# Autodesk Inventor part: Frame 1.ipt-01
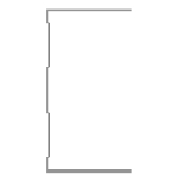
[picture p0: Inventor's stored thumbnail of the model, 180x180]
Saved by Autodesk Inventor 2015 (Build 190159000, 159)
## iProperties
Created: 2015-04
Part Number: Frame 1.ipt-01
Material: Aluminum 6061
Description: Kévin Novo
Document SubType Name: Modeling
Standard: Kevin
Designer: suporte
Standards Organization: Kevin
Language: en-US
Size Designation: (Unnamed 1)
Categories: <MemberInstance><Categories><Category DisplayName="Structural Shapes" InternalName="089c4875-fa83-4c05-b084-43b9cc11f5ed" Mnemonic="GRDR"><CategoryParameter Dis
Density: 2.7 g/cm^3
Appearance: Aluminum - Flat
IsCustomPart: 1
G_L: 1150,000 mm
G_W: 50,000 mm
G_H: 75,000 mm
+3D70875A-E5A9-4FDA-85E3-2CF6FFD64956+CUTDETAIL1: Cut
+E4C8F863-C9A0-4110-9EB7-EA6FC54E2E86+CUTDETAIL2: Cut
_CCFamilyMember: 1
_CCFamilyDisplayName: Kévin - Kévin Novo
_FrameMemberDoc: Frame Member File
_Version: 15.0.0
_GetPNFromCC: 1
Author: suporte
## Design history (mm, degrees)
node "Start Plane"
node "End Plane"
sketch "Sketch"
  geometry: L1 (24.7, 37.5)-(24.7, 36.9); L2 (24.7, 36.9)-(-24.7, 36.9); L3 (-24.7, -36.9)-(24.7, -36.9); L4 (24.7, -36.9)-(24.7, -37.5); L5 (24.7, -37.5)-(-25.3, -37.5); L6 (-25.3, 37.5)-(24.7, 37.5); L7 (-24.7, 36.9)-(-24.7, 31.9); L8 (-24.7, 31.9)-(-23.3, 30.5); L9 (-23.3, 30.5)-(-23.3, 10.934); L10 (-23.3, 10.934)-(-24.7, 9.534); L11 (-24.7, 9.534)-(-24.7, -9.534); L12 (-24.7, -9.534)-(-23.3, -10.934); L13 (-23.3, -10.934)-(-23.3, -30.5); L14 (-23.3, -30.5)-(-24.7, -31.9); L15 (-24.7, -31.9)-(-24.7, -36.9); L16 (-25.3, -37.5)-(-25.3, -31.651); L17 (-25.3, -31.651)-(-23.9, -30.251); L18 (-23.9, -30.251)-(-23.9, -11.183); L19 (-23.9, -11.183)-(-25.3, -9.783); L20 (-25.3, -9.783)-(-25.3, 9.783); L21 (-25.3, 9.783)-(-23.9, 11.183); L22 (-23.9, 11.183)-(-23.9, 30.251); L23 (-23.9, 30.251)-(-25.3, 31.651); L24 (-25.3, 31.651)-(-25.3, 37.5); L25 (-25.3, 0)-(30.37, 0); 3 further points
  constraints: 50 end point, 10 point on line, 9 parallel, 5 perpendicular, 4 equal length, 3 midpoint, 3 vertical, 2 vertical alignment, 1 collinear, 1 horizontal, 1 horizontal alignment
  dimensions: "d3" = 0.6 distance of L1.start L1.end (= d6); "d5" = 75 distance between parallel lines of L5 L6; "d6" = 0.6 distance between parallel lines of L24 L7 (= d8); "d7" = 0.6 distance between parallel lines of L8 L23 (= d8); "d8" = 0.6 distance between parallel lines of L22 L9 (= d12); "Espessura" = 0.6 distance between parallel lines of L17 L14; "d10" = 0.6 distance between parallel lines of L13 L18 (= Espessura); "d11" = 0.6 distance between parallel lines of L12 L19 (= Espessura); "d12" = 0.6 distance between parallel lines of L21 L10 (= d11); "d13" = 5 distance of L2.end L7.end; "d15" = 135 deg angle of L9 L8; "d16" = 2 distance between parallel lines of L24 L9; "d17" = 50 distance of L6.start L1.start
extrude "Body" join sketch "Sketch" stored distance "d24" = 0.13; taper "d25" = 0 deg
node "Driven Length"
  sketch "Sketch10"
    geometry: L1 (0, 0)-(10, 0) reference
    constraints: 2 end point, 1 horizontal
  workplane "Work Plane7"
  sketch "Sketch11"
    geometry: L1 (-2, 37.5)-(12, 37.5) reference; L2 (-2, 1187.5)-(12, 1187.5) reference
    dimensions: "d27" = 1150 distance between parallel lines of L1 L2 (derived)
workplane "Work Plane8"
split "Split1"
workplane "Work Plane9"
split "Split2"
body "Solid1"
other parameters: "G_OFFSET_START" = -37.5 [user parameter; used in 1 equation term], "G_OFFSET_END" = -12.5 [user parameter; used in 1 equation term], "d22" = 37.5 (= -G_OFFSET_START), "d23" = 1187.5 (= tamanho + G_OFFSET_END), "G_L" = 1150 (= d27) [user parameter], "d34" = 90 deg
